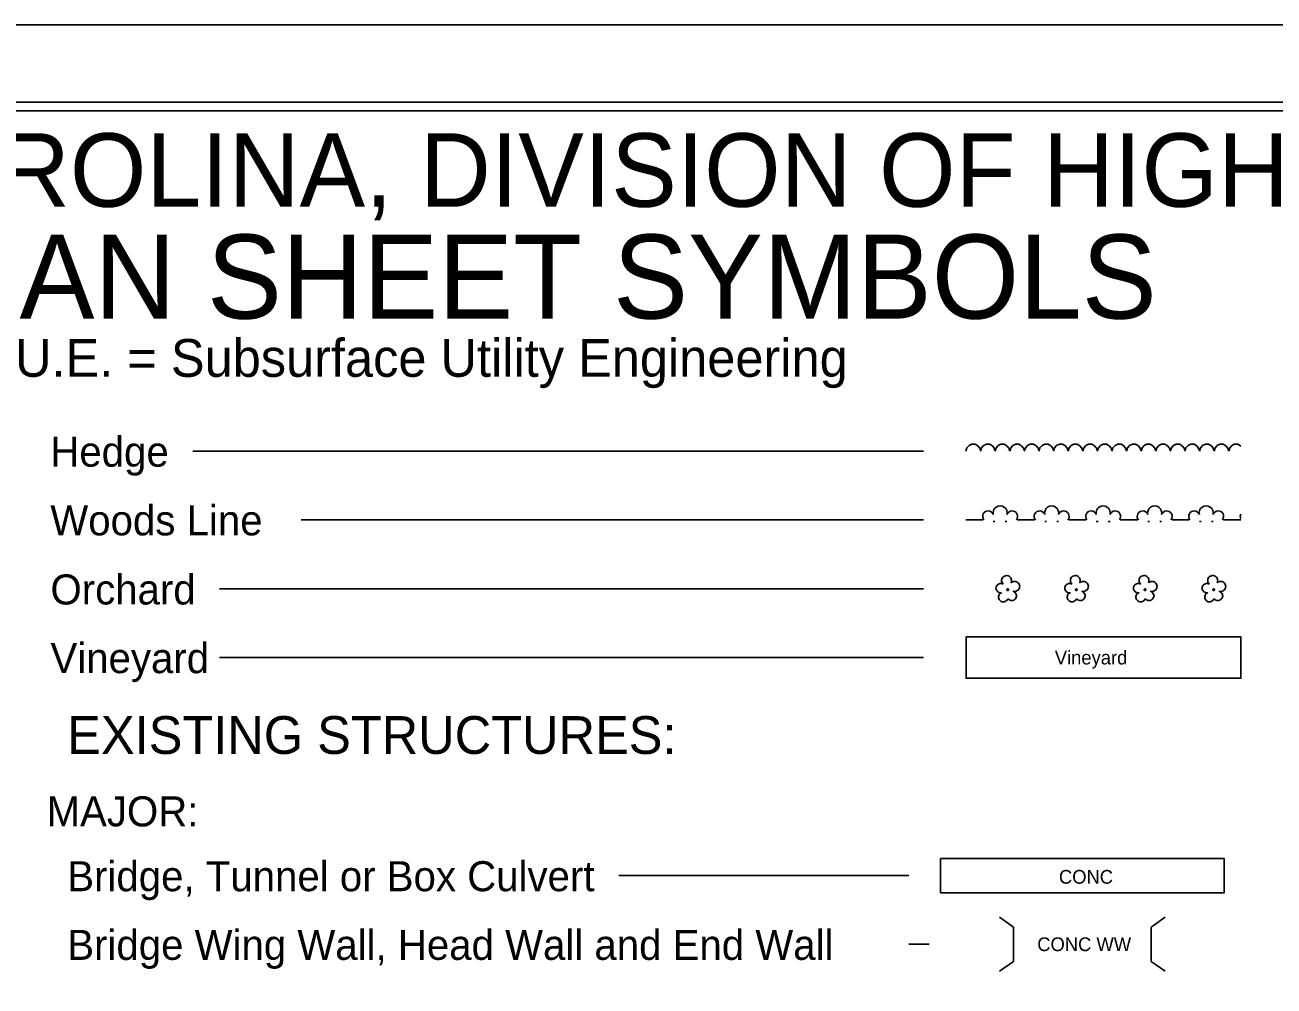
# Model space of a CAD drawing. Extents: x 2014488 to 2016172, y 399324 to 400424.
# Drawn here: x 2015410.6 to 2015774.2, y 400144.5 to 400424.4 of the extents above; entities that cross this region are included whole.
import ezdxf

# ---------------------------------------------------------------- set-up
doc = ezdxf.new("R2010")
doc.units = 0
for name, color, linetype in [('Sheet Plot Border Inside CELL', 7, 'Continuous'), ('Sheet Plot Border Outside CELL', 7, 'Continuous'), ('Sheet Symbology CELL', 7, 'Continuous')]:
    doc.layers.add(name, color=color, linetype=linetype)

msp = doc.modelspace()

# ---------------------------------------------------------------- linework, layer by layer
at = {"layer": 'Sheet Plot Border Inside CELL'}
msp.add_lwpolyline([(2014500.85, 399346.86), (2016167.35, 399346.86), (2016167.35, 400401.96), (2014500.85, 400401.96)], close=True, dxfattribs=at)
at = {"layer": 'Sheet Plot Border Outside CELL'}
msp.add_lwpolyline([(2014487.85, 399324.41), (2016171.85, 399324.41), (2016171.85, 400424.41), (2014487.85, 400424.41)], close=True, dxfattribs=at)
at = {"layer": 'Sheet Symbology CELL'}
for p, q in [((2015672.13, 400300.27), (2015459.44, 400300.27)), ((2015684.52, 400300.27), (2015684.82, 400301.22)), ((2015684.82, 400301.22), (2015685.42, 400301.87)), ((2015685.42, 400301.87), (2015686.22, 400302.32)), ((2015686.22, 400302.32), (2015687.17, 400302.32)), ((2015687.17, 400302.32), (2015687.97, 400301.82)), ((2015687.97, 400301.82), (2015688.52, 400301.17)), ((2015688.52, 400301.17), (2015688.72, 400300.32)), ((2015688.77, 400300.27), (2015689.07, 400301.22)), ((2015689.07, 400301.22), (2015689.67, 400301.87)), ((2015689.67, 400301.87), (2015690.47, 400302.32)), ((2015690.47, 400302.32), (2015691.42, 400302.32)), ((2015691.42, 400302.32), (2015692.22, 400301.82)), ((2015692.22, 400301.82), (2015692.77, 400301.17)), ((2015692.77, 400301.17), (2015692.97, 400300.32)), ((2015693.02, 400300.27), (2015693.32, 400301.22)), ((2015693.32, 400301.22), (2015693.92, 400301.87)), ((2015693.92, 400301.87), (2015694.72, 400302.32)), ((2015694.72, 400302.32), (2015695.67, 400302.32)), ((2015695.67, 400302.32), (2015696.47, 400301.82)), ((2015696.47, 400301.82), (2015697.02, 400301.17)), ((2015697.02, 400301.17), (2015697.22, 400300.32)), ((2015697.27, 400300.27), (2015697.57, 400301.22)), ((2015697.57, 400301.22), (2015698.17, 400301.87)), ((2015698.17, 400301.87), (2015698.97, 400302.32)), ((2015698.97, 400302.32), (2015699.92, 400302.32)), ((2015699.92, 400302.32), (2015700.72, 400301.82)), ((2015700.72, 400301.82), (2015701.27, 400301.17)), ((2015701.27, 400301.17), (2015701.47, 400300.32)), ((2015701.52, 400300.27), (2015701.82, 400301.22)), ((2015701.82, 400301.22), (2015702.42, 400301.87)), ((2015702.42, 400301.87), (2015703.22, 400302.32)), ((2015703.22, 400302.32), (2015704.17, 400302.32)), ((2015704.17, 400302.32), (2015704.97, 400301.82)), ((2015704.97, 400301.82), (2015705.52, 400301.17)), ((2015705.52, 400301.17), (2015705.72, 400300.32)), ((2015705.77, 400300.27), (2015706.07, 400301.22)), ((2015706.07, 400301.22), (2015706.67, 400301.87)), ((2015706.67, 400301.87), (2015707.47, 400302.32)), ((2015707.47, 400302.32), (2015708.42, 400302.32)), ((2015708.42, 400302.32), (2015709.22, 400301.82)), ((2015709.22, 400301.82), (2015709.77, 400301.17)), ((2015709.77, 400301.17), (2015709.97, 400300.32)), ((2015710.02, 400300.27), (2015710.32, 400301.22)), ((2015710.32, 400301.22), (2015710.92, 400301.87)), ((2015710.92, 400301.87), (2015711.72, 400302.32)), ((2015711.72, 400302.32), (2015712.67, 400302.32)), ((2015712.67, 400302.32), (2015713.47, 400301.82)), ((2015713.47, 400301.82), (2015714.02, 400301.17)), ((2015714.02, 400301.17), (2015714.22, 400300.32)), ((2015714.27, 400300.27), (2015714.57, 400301.22)), ((2015714.57, 400301.22), (2015715.17, 400301.87)), ((2015715.17, 400301.87), (2015715.97, 400302.32)), ((2015715.97, 400302.32), (2015716.92, 400302.32)), ((2015716.92, 400302.32), (2015717.72, 400301.82)), ((2015717.72, 400301.82), (2015718.27, 400301.17)), ((2015718.27, 400301.17), (2015718.47, 400300.32)), ((2015718.52, 400300.27), (2015718.82, 400301.22)), ((2015718.82, 400301.22), (2015719.42, 400301.87)), ((2015719.42, 400301.87), (2015720.22, 400302.32)), ((2015720.22, 400302.32), (2015721.17, 400302.32)), ((2015721.17, 400302.32), (2015721.97, 400301.82)), ((2015721.97, 400301.82), (2015722.52, 400301.17)), ((2015722.52, 400301.17), (2015722.72, 400300.32)), ((2015722.77, 400300.27), (2015723.07, 400301.22)), ((2015723.07, 400301.22), (2015723.67, 400301.87)), ((2015723.67, 400301.87), (2015724.47, 400302.32)), ((2015724.47, 400302.32), (2015725.42, 400302.32)), ((2015725.42, 400302.32), (2015726.22, 400301.82)), ((2015726.22, 400301.82), (2015726.77, 400301.17)), ((2015726.77, 400301.17), (2015726.97, 400300.32)), ((2015727.02, 400300.27), (2015727.32, 400301.22)), ((2015727.32, 400301.22), (2015727.92, 400301.87)), ((2015727.92, 400301.87), (2015728.72, 400302.32)), ((2015728.72, 400302.32), (2015729.67, 400302.32)), ((2015729.67, 400302.32), (2015730.47, 400301.82)), ((2015730.47, 400301.82), (2015731.02, 400301.17)), ((2015731.02, 400301.17), (2015731.22, 400300.32)), ((2015731.27, 400300.27), (2015731.57, 400301.22)), ((2015731.57, 400301.22), (2015732.17, 400301.87)), ((2015732.17, 400301.87), (2015732.97, 400302.32)), ((2015732.97, 400302.32), (2015733.92, 400302.32)), ((2015733.92, 400302.32), (2015734.72, 400301.82)), ((2015734.72, 400301.82), (2015735.27, 400301.17)), ((2015735.27, 400301.17), (2015735.47, 400300.32)), ((2015735.52, 400300.27), (2015735.82, 400301.22)), ((2015735.82, 400301.22), (2015736.42, 400301.87)), ((2015736.42, 400301.87), (2015737.22, 400302.32)), ((2015737.22, 400302.32), (2015738.17, 400302.32)), ((2015738.17, 400302.32), (2015738.97, 400301.82)), ((2015738.97, 400301.82), (2015739.52, 400301.17)), ((2015739.52, 400301.17), (2015739.72, 400300.32)), ((2015739.77, 400300.27), (2015740.07, 400301.22)), ((2015740.07, 400301.22), (2015740.67, 400301.87)), ((2015740.67, 400301.87), (2015741.47, 400302.32)), ((2015741.47, 400302.32), (2015742.42, 400302.32)), ((2015742.42, 400302.32), (2015743.22, 400301.82)), ((2015743.22, 400301.82), (2015743.77, 400301.17)), ((2015743.77, 400301.17), (2015743.97, 400300.32)), ((2015744.02, 400300.27), (2015744.32, 400301.22)), ((2015744.32, 400301.22), (2015744.92, 400301.87)), ((2015744.92, 400301.87), (2015745.72, 400302.32)), ((2015745.72, 400302.32), (2015746.67, 400302.32)), ((2015746.67, 400302.32), (2015747.47, 400301.82)), ((2015747.47, 400301.82), (2015748.02, 400301.17)), ((2015748.02, 400301.17), (2015748.22, 400300.32)), ((2015748.27, 400300.27), (2015748.57, 400301.22)), ((2015748.57, 400301.22), (2015749.17, 400301.87)), ((2015749.17, 400301.87), (2015749.97, 400302.32)), ((2015749.97, 400302.32), (2015750.92, 400302.32)), ((2015750.92, 400302.32), (2015751.72, 400301.82)), ((2015751.72, 400301.82), (2015752.27, 400301.17)), ((2015752.27, 400301.17), (2015752.47, 400300.32)), ((2015752.52, 400300.27), (2015752.82, 400301.22)), ((2015752.82, 400301.22), (2015753.42, 400301.87)), ((2015753.42, 400301.87), (2015754.22, 400302.32)), ((2015754.22, 400302.32), (2015755.17, 400302.32)), ((2015755.17, 400302.32), (2015755.97, 400301.82)), ((2015755.97, 400301.82), (2015756.52, 400301.17)), ((2015756.52, 400301.17), (2015756.72, 400300.32)), ((2015756.77, 400300.27), (2015757.07, 400301.22)), ((2015757.07, 400301.22), (2015757.67, 400301.87)), ((2015757.67, 400301.87), (2015758.47, 400302.32)), ((2015758.47, 400302.32), (2015759.42, 400302.32)), ((2015759.42, 400302.32), (2015760.22, 400301.82)), ((2015760.22, 400301.82), (2015760.77, 400301.17)), ((2015760.77, 400301.17), (2015760.97, 400300.32)), ((2015761.02, 400300.27), (2015761.32, 400301.22)), ((2015761.32, 400301.22), (2015761.92, 400301.87)), ((2015761.92, 400301.87), (2015762.72, 400302.32)), ((2015762.72, 400302.32), (2015763.67, 400302.32)), ((2015763.67, 400302.32), (2015764.47, 400301.82)), ((2015764.47, 400301.82), (2015764.52, 400301.77)), ((2015672.13, 400280.27), (2015491, 400280.27)), ((2015684.52, 400280.27), (2015689.52, 400280.27)), ((2015692.47, 400279.77), (2015692.97, 400279.77)), ((2015695.97, 400279.77), (2015696.47, 400279.77)), ((2015699.52, 400280.27), (2015704.52, 400280.27)), ((2015707.47, 400279.77), (2015707.97, 400279.77)), ((2015710.97, 400279.77), (2015711.47, 400279.77)), ((2015714.52, 400280.27), (2015719.52, 400280.27)), ((2015722.47, 400279.77), (2015722.97, 400279.77)), ((2015725.97, 400279.77), (2015726.47, 400279.77)), ((2015729.52, 400280.27), (2015734.52, 400280.27)), ((2015737.47, 400279.77), (2015737.97, 400279.77)), ((2015740.97, 400279.77), (2015741.47, 400279.77)), ((2015744.52, 400280.27), (2015749.52, 400280.27)), ((2015752.47, 400279.77), (2015752.97, 400279.77)), ((2015755.97, 400279.77), (2015756.47, 400279.77)), ((2015759.52, 400280.27), (2015764.52, 400280.27)), ((2015672.18, 400260.13), (2015467.24, 400260.13)), ((2015672.18, 400240.13), (2015467.24, 400240.13)), ((2015667.86, 400176.62), (2015583.43, 400176.62)), ((2015694.31, 400164.49), (2015698.41, 400161.62)), ((2015742.51, 400164.49), (2015738.41, 400161.62)), ((2015698.41, 400161.62), (2015698.41, 400151.62)), ((2015738.41, 400161.62), (2015738.41, 400151.62)), ((2015667.86, 400156.62), (2015673.85, 400156.62)), ((2015694.31, 400148.76), (2015698.41, 400151.62)), ((2015742.51, 400148.76), (2015738.41, 400151.62))]:
    msp.add_line(p, q, dxfattribs=at)
msp.add_lwpolyline([(2016154.85, 400399.41), (2014654.85, 400399.41), (2014654.85, 399350.43), (2016154.85, 399350.43)], close=True, dxfattribs=at)
for points in [[(2015697.62, 400261.88), (2015697.77, 400262.18), (2015697.82, 400262.48), (2015697.77, 400262.78), (2015697.72, 400263.08), (2015697.57, 400263.33), (2015697.42, 400263.58), (2015697.17, 400263.78), (2015696.92, 400263.93), (2015696.57, 400264.03), (2015696.32, 400264.03), (2015696.02, 400263.98), (2015695.72, 400263.88), (2015695.47, 400263.73), (2015695.22, 400263.53), (2015695.07, 400263.23), (2015694.97, 400262.98), (2015694.92, 400262.68), (2015694.92, 400262.38), (2015694.97, 400262.08), (2015695.12, 400261.83), (2015695.32, 400261.53), (2015695.07, 400261.68), (2015694.77, 400261.73), (2015694.47, 400261.73), (2015694.22, 400261.63), (2015693.97, 400261.53), (2015693.72, 400261.33), (2015693.52, 400261.13), (2015693.37, 400260.88), (2015693.32, 400260.63), (2015693.27, 400260.28), (2015693.32, 400260.03), (2015693.42, 400259.78), (2015693.62, 400259.53), (2015693.77, 400259.33), (2015694.02, 400259.18), (2015694.32, 400259.03), (2015694.57, 400258.98), (2015694.87, 400258.98), (2015694.62, 400258.88), (2015694.37, 400258.68), (2015694.22, 400258.48), (2015694.12, 400258.18), (2015694.02, 400257.88), (2015694.02, 400257.63), (2015694.07, 400257.33), (2015694.22, 400257.08), (2015694.37, 400256.83), (2015694.57, 400256.63), (2015694.82, 400256.48), (2015695.07, 400256.38), (2015695.37, 400256.38), (2015695.67, 400256.38), (2015695.92, 400256.43), (2015696.17, 400256.63), (2015696.42, 400256.78), (2015696.67, 400257.23)], [(2015717.62, 400261.88), (2015717.77, 400262.18), (2015717.82, 400262.48), (2015717.77, 400262.78), (2015717.72, 400263.08), (2015717.57, 400263.33), (2015717.42, 400263.58), (2015717.17, 400263.78), (2015716.92, 400263.93), (2015716.57, 400264.03), (2015716.32, 400264.03), (2015716.02, 400263.98), (2015715.72, 400263.88), (2015715.47, 400263.73), (2015715.22, 400263.53), (2015715.07, 400263.23), (2015714.97, 400262.98), (2015714.92, 400262.68), (2015714.92, 400262.38), (2015714.97, 400262.08), (2015715.12, 400261.83), (2015715.32, 400261.53), (2015715.07, 400261.68), (2015714.77, 400261.73), (2015714.47, 400261.73), (2015714.22, 400261.63), (2015713.97, 400261.53), (2015713.72, 400261.33), (2015713.52, 400261.13), (2015713.37, 400260.88), (2015713.32, 400260.63), (2015713.27, 400260.28), (2015713.32, 400260.03), (2015713.42, 400259.78), (2015713.62, 400259.53), (2015713.77, 400259.33), (2015714.02, 400259.18), (2015714.32, 400259.03), (2015714.57, 400258.98), (2015714.87, 400258.98), (2015714.62, 400258.88), (2015714.37, 400258.68), (2015714.22, 400258.48), (2015714.12, 400258.18), (2015714.02, 400257.88), (2015714.02, 400257.63), (2015714.07, 400257.33), (2015714.22, 400257.08), (2015714.37, 400256.83), (2015714.57, 400256.63), (2015714.82, 400256.48), (2015715.07, 400256.38), (2015715.37, 400256.38), (2015715.67, 400256.38), (2015715.92, 400256.43), (2015716.17, 400256.63), (2015716.42, 400256.78), (2015716.67, 400257.23)], [(2015737.62, 400261.88), (2015737.77, 400262.18), (2015737.82, 400262.48), (2015737.77, 400262.78), (2015737.72, 400263.08), (2015737.57, 400263.33), (2015737.42, 400263.58), (2015737.17, 400263.78), (2015736.92, 400263.93), (2015736.57, 400264.03), (2015736.32, 400264.03), (2015736.02, 400263.98), (2015735.72, 400263.88), (2015735.47, 400263.73), (2015735.22, 400263.53), (2015735.07, 400263.23), (2015734.97, 400262.98), (2015734.92, 400262.68), (2015734.92, 400262.38), (2015734.97, 400262.08), (2015735.12, 400261.83), (2015735.32, 400261.53), (2015735.07, 400261.68), (2015734.77, 400261.73), (2015734.47, 400261.73), (2015734.22, 400261.63), (2015733.97, 400261.53), (2015733.72, 400261.33), (2015733.52, 400261.13), (2015733.37, 400260.88), (2015733.32, 400260.63), (2015733.27, 400260.28), (2015733.32, 400260.03), (2015733.42, 400259.78), (2015733.62, 400259.53), (2015733.77, 400259.33), (2015734.02, 400259.18), (2015734.32, 400259.03), (2015734.57, 400258.98), (2015734.87, 400258.98), (2015734.62, 400258.88), (2015734.37, 400258.68), (2015734.22, 400258.48), (2015734.12, 400258.18), (2015734.02, 400257.88), (2015734.02, 400257.63), (2015734.07, 400257.33), (2015734.22, 400257.08), (2015734.37, 400256.83), (2015734.57, 400256.63), (2015734.82, 400256.48), (2015735.07, 400256.38), (2015735.37, 400256.38), (2015735.67, 400256.38), (2015735.92, 400256.43), (2015736.17, 400256.63), (2015736.42, 400256.78), (2015736.67, 400257.23)], [(2015757.62, 400261.88), (2015757.77, 400262.18), (2015757.82, 400262.48), (2015757.77, 400262.78), (2015757.72, 400263.08), (2015757.57, 400263.33), (2015757.42, 400263.58), (2015757.17, 400263.78), (2015756.92, 400263.93), (2015756.57, 400264.03), (2015756.32, 400264.03), (2015756.02, 400263.98), (2015755.72, 400263.88), (2015755.47, 400263.73), (2015755.22, 400263.53), (2015755.07, 400263.23), (2015754.97, 400262.98), (2015754.92, 400262.68), (2015754.92, 400262.38), (2015754.97, 400262.08), (2015755.12, 400261.83), (2015755.32, 400261.53), (2015755.07, 400261.68), (2015754.77, 400261.73), (2015754.47, 400261.73), (2015754.22, 400261.63), (2015753.97, 400261.53), (2015753.72, 400261.33), (2015753.52, 400261.13), (2015753.37, 400260.88), (2015753.32, 400260.63), (2015753.27, 400260.28), (2015753.32, 400260.03), (2015753.42, 400259.78), (2015753.62, 400259.53), (2015753.77, 400259.33), (2015754.02, 400259.18), (2015754.32, 400259.03), (2015754.57, 400258.98), (2015754.87, 400258.98), (2015754.62, 400258.88), (2015754.37, 400258.68), (2015754.22, 400258.48), (2015754.12, 400258.18), (2015754.02, 400257.88), (2015754.02, 400257.63), (2015754.07, 400257.33), (2015754.22, 400257.08), (2015754.37, 400256.83), (2015754.57, 400256.63), (2015754.82, 400256.48), (2015755.07, 400256.38), (2015755.37, 400256.38), (2015755.67, 400256.38), (2015755.92, 400256.43), (2015756.17, 400256.63), (2015756.42, 400256.78), (2015756.67, 400257.23)], [(2015696.67, 400257.23), (2015697.27, 400256.88), (2015697.57, 400256.78), (2015697.87, 400256.73), (2015698.17, 400256.78), (2015698.42, 400256.88), (2015698.67, 400257.03), (2015698.92, 400257.23), (2015699.07, 400257.48), (2015699.17, 400257.73), (2015699.27, 400258.03), (2015699.22, 400258.33), (2015699.17, 400258.63), (2015698.97, 400258.93), (2015698.82, 400259.13), (2015698.57, 400259.28), (2015698.27, 400259.43), (2015698.57, 400259.38), (2015698.92, 400259.38), (2015699.17, 400259.48), (2015699.47, 400259.63), (2015699.72, 400259.78), (2015699.92, 400260.03), (2015700.07, 400260.33), (2015700.12, 400260.63), (2015700.17, 400260.93), (2015700.12, 400261.23), (2015700.02, 400261.53), (2015699.82, 400261.78), (2015699.57, 400262.03), (2015699.32, 400262.18), (2015699.02, 400262.28), (2015698.72, 400262.33), (2015698.42, 400262.33), (2015698.12, 400262.23), (2015697.87, 400262.08), (2015697.62, 400261.88)], [(2015716.67, 400257.23), (2015717.27, 400256.88), (2015717.57, 400256.78), (2015717.87, 400256.73), (2015718.17, 400256.78), (2015718.42, 400256.88), (2015718.67, 400257.03), (2015718.92, 400257.23), (2015719.07, 400257.48), (2015719.17, 400257.73), (2015719.27, 400258.03), (2015719.22, 400258.33), (2015719.17, 400258.63), (2015718.97, 400258.93), (2015718.82, 400259.13), (2015718.57, 400259.28), (2015718.27, 400259.43), (2015718.57, 400259.38), (2015718.92, 400259.38), (2015719.17, 400259.48), (2015719.47, 400259.63), (2015719.72, 400259.78), (2015719.92, 400260.03), (2015720.07, 400260.33), (2015720.12, 400260.63), (2015720.17, 400260.93), (2015720.12, 400261.23), (2015720.02, 400261.53), (2015719.82, 400261.78), (2015719.57, 400262.03), (2015719.32, 400262.18), (2015719.02, 400262.28), (2015718.72, 400262.33), (2015718.42, 400262.33), (2015718.12, 400262.23), (2015717.87, 400262.08), (2015717.62, 400261.88)], [(2015736.67, 400257.23), (2015737.27, 400256.88), (2015737.57, 400256.78), (2015737.87, 400256.73), (2015738.17, 400256.78), (2015738.42, 400256.88), (2015738.67, 400257.03), (2015738.92, 400257.23), (2015739.07, 400257.48), (2015739.17, 400257.73), (2015739.27, 400258.03), (2015739.22, 400258.33), (2015739.17, 400258.63), (2015738.97, 400258.93), (2015738.82, 400259.13), (2015738.57, 400259.28), (2015738.27, 400259.43), (2015738.57, 400259.38), (2015738.92, 400259.38), (2015739.17, 400259.48), (2015739.47, 400259.63), (2015739.72, 400259.78), (2015739.92, 400260.03), (2015740.07, 400260.33), (2015740.12, 400260.63), (2015740.17, 400260.93), (2015740.12, 400261.23), (2015740.02, 400261.53), (2015739.82, 400261.78), (2015739.57, 400262.03), (2015739.32, 400262.18), (2015739.02, 400262.28), (2015738.72, 400262.33), (2015738.42, 400262.33), (2015738.12, 400262.23), (2015737.87, 400262.08), (2015737.62, 400261.88)], [(2015756.67, 400257.23), (2015757.27, 400256.88), (2015757.57, 400256.78), (2015757.87, 400256.73), (2015758.17, 400256.78), (2015758.42, 400256.88), (2015758.67, 400257.03), (2015758.92, 400257.23), (2015759.07, 400257.48), (2015759.17, 400257.73), (2015759.27, 400258.03), (2015759.22, 400258.33), (2015759.17, 400258.63), (2015758.97, 400258.93), (2015758.82, 400259.13), (2015758.57, 400259.28), (2015758.27, 400259.43), (2015758.57, 400259.38), (2015758.92, 400259.38), (2015759.17, 400259.48), (2015759.47, 400259.63), (2015759.72, 400259.78), (2015759.92, 400260.03), (2015760.07, 400260.33), (2015760.12, 400260.63), (2015760.17, 400260.93), (2015760.12, 400261.23), (2015760.02, 400261.53), (2015759.82, 400261.78), (2015759.57, 400262.03), (2015759.32, 400262.18), (2015759.02, 400262.28), (2015758.72, 400262.33), (2015758.42, 400262.33), (2015758.12, 400262.23), (2015757.87, 400262.08), (2015757.62, 400261.88)], [(2015696.77, 400260.13), (2015696.62, 400260.13), (2015696.52, 400260.08), (2015696.42, 400260.03), (2015696.42, 400259.88), (2015696.42, 400259.78), (2015696.52, 400259.68), (2015696.67, 400259.68), (2015696.77, 400259.68), (2015696.87, 400259.78), (2015696.92, 400259.93), (2015696.87, 400260.03), (2015696.77, 400260.13)], [(2015716.77, 400260.13), (2015716.62, 400260.13), (2015716.52, 400260.08), (2015716.42, 400260.03), (2015716.42, 400259.88), (2015716.42, 400259.78), (2015716.52, 400259.68), (2015716.67, 400259.68), (2015716.77, 400259.68), (2015716.87, 400259.78), (2015716.92, 400259.93), (2015716.87, 400260.03), (2015716.77, 400260.13)], [(2015736.77, 400260.13), (2015736.62, 400260.13), (2015736.52, 400260.08), (2015736.42, 400260.03), (2015736.42, 400259.88), (2015736.42, 400259.78), (2015736.52, 400259.68), (2015736.67, 400259.68), (2015736.77, 400259.68), (2015736.87, 400259.78), (2015736.92, 400259.93), (2015736.87, 400260.03), (2015736.77, 400260.13)], [(2015756.77, 400260.13), (2015756.62, 400260.13), (2015756.52, 400260.08), (2015756.42, 400260.03), (2015756.42, 400259.88), (2015756.42, 400259.78), (2015756.52, 400259.68), (2015756.67, 400259.68), (2015756.77, 400259.68), (2015756.87, 400259.78), (2015756.92, 400259.93), (2015756.87, 400260.03), (2015756.77, 400260.13)], [(2015684.57, 400246.13), (2015764.57, 400246.13), (2015764.57, 400234.13), (2015684.57, 400234.13), (2015684.57, 400246.13)], [(2015677.16, 400181.62), (2015759.66, 400181.62), (2015759.66, 400171.62), (2015677.16, 400171.62), (2015677.16, 400181.62)]]:
    msp.add_lwpolyline(points, dxfattribs=at)
for centre, radius, start, end in [((2015690.97, 400281.28), 1.58, 18.4349, 219.2315), ((2015694.47, 400282.28), 2.06, 345.9638, 194.0362), ((2015697.97, 400281.28), 1.58, 320.7685, 161.565), ((2015705.97, 400281.28), 1.58, 18.4349, 219.2315), ((2015709.47, 400282.28), 2.06, 345.9638, 194.0362), ((2015712.97, 400281.28), 1.58, 320.7685, 161.565), ((2015720.97, 400281.28), 1.58, 18.4349, 219.2315), ((2015724.47, 400282.28), 2.06, 345.9638, 194.0362), ((2015727.97, 400281.28), 1.58, 320.7685, 161.565), ((2015735.97, 400281.28), 1.58, 18.4349, 219.2315), ((2015739.47, 400282.28), 2.06, 345.9638, 194.0362), ((2015742.97, 400281.28), 1.58, 320.7685, 161.565), ((2015750.97, 400281.28), 1.58, 18.4349, 219.2315), ((2015754.47, 400282.28), 2.06, 345.9638, 194.0362), ((2015757.97, 400281.28), 1.58, 320.7685, 161.565), ((2015765.97, 400281.28), 1.58, 156.251, 203.749)]:
    msp.add_arc(centre, radius, start, end, dxfattribs=at)

# ---------------------------------------------------------------- texts
for s, height, rotation, p in [('STATE OF NORTH CAROLINA, DIVISION OF HIGHWAYS', 21.419, 360, (2015105.41, 400371.45)), ('CONVENTIONAL  PLAN SHEET SYMBOLS', 24.4803, 360, (2015092.46, 400338.88)), ('*S.U.E. = Subsurface Utility Engineering', 11, 360, (2015388.07, 400321.92)), ('Hedge', 8.75, 360, (2015417.96, 400295.74)), ('Woods Line', 8.75, 360, (2015417.96, 400275.74)), ('Orchard', 8.75, 360, (2015418.01, 400255.6)), ('Vineyard', 8.75, 360, (2015418.01, 400235.6)), ('Vineyard', 4, 0, (2015710.39, 400238.13)), ('EXISTING STRUCTURES:', 11, 360, (2015422.9, 400212.07)), ('MAJOR:', 8.75, 360, (2015416.87, 400190.96)), ('Bridge, Tunnel or Box Culvert', 8.75, 360, (2015422.9, 400172.07)), ('CONC', 4, 360, (2015711.6, 400174.26)), ('Bridge Wing Wall, Head Wall and End Wall', 8.75, 360, (2015422.9, 400152.07)), ('CONC WW', 4, 0, (2015705.28, 400154.62))]:
    msp.add_text(s, height=height, rotation=rotation, dxfattribs=at).set_placement(p)

doc.saveas('drawing.dxf')
